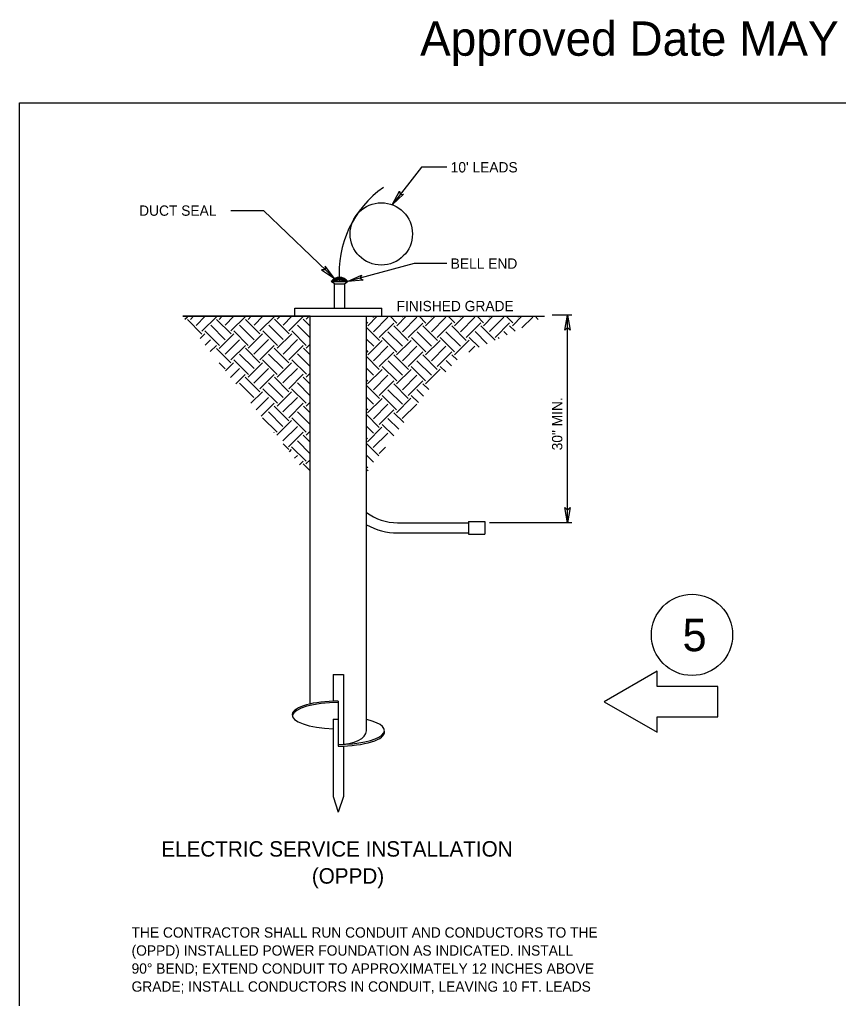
# Model space of a CAD drawing. Extents: x 99992 to 113392, y 99794 to 102182.
# Drawn here: x 105092 to 106046, y 101041 to 102182 of the extents above; entities that cross this region are included whole.
import ezdxf

# ---------------------------------------------------------------- set-up
doc = ezdxf.new("R2010")
doc.units = 0
for name, color, linetype in [('Border Line', 7, 'Continuous'), ('Border Organizer Shape', 7, 'Continuous'), ('Default', 7, 'Continuous'), ('QM Aggregate Gravel', 7, 'Continuous')]:
    doc.layers.add(name, color=color, linetype=linetype)

msp = doc.modelspace()

# ---------------------------------------------------------------- linework, layer by layer
at = {"layer": 'Border Organizer Shape'}
for p, q in [((105560.5, 102010), (105526.1, 101966.4)), ((105590, 102010), (105560.5, 102010)), ((105338.2, 101959.5), (105376.3, 101959.5)), ((105376.3, 101959.5), (105459, 101880.2)), ((105551.9, 101897.8), (105474.3, 101876.7)), ((105590, 101897.8), (105551.9, 101897.8)), ((105455.4, 101876.7), (105474.3, 101876.8)), ((105458.9, 101874), (105455.4, 101876.7)), ((105458.8, 101874), (105458.8, 101845.8)), ((105458.8, 101874), (105470.7, 101874)), ((105470.7, 101874), (105474.3, 101876.7)), ((105470.7, 101874), (105470.7, 101845.8)), ((105412.7, 101845.8), (105514.3, 101845.8)), ((105412.7, 101836.3), (105412.7, 101845.8)), ((105514.3, 101836.3), (105514.3, 101845.8)), ((105282.3, 101836.3), (105430.7, 101836.3)), ((105430.7, 101836.3), (105282.3, 101836.3)), ((105284.9, 101833), (105287.8, 101835.9)), ((105287.8, 101832.6), (105304.7, 101815.7)), ((105291.1, 101836.3), (105291.4, 101836)), ((105291.2, 101832.6), (105294.9, 101836.3)), ((105297.9, 101825.8), (105308.4, 101836.3)), ((105304.7, 101819), (105321.6, 101835.9)), ((105321.7, 101832.7), (105338.6, 101815.8)), ((105324.7, 101836.3), (105325, 101835.9)), ((105324.9, 101832.7), (105328.4, 101836.3)), ((105331.6, 101825.9), (105341.9, 101836.3)), ((105338.4, 101819.2), (105355.3, 101836.1)), ((105355.3, 101832.7), (105372.2, 101815.8)), ((105358.7, 101832.7), (105362.2, 101836.3)), ((105358.7, 101836.3), (105358.9, 101836.1)), ((105365.4, 101825.9), (105375.7, 101836.3)), ((105372.2, 101819.2), (105389.1, 101836.1)), ((105389.2, 101832.8), (105406.1, 101815.9)), ((105392.3, 101832.8), (105395.8, 101836.3)), ((105392.3, 101836.3), (105392.4, 101836.1)), ((105399.1, 101826), (105409.3, 101836.3)), ((105405.8, 101819.3), (105422.7, 101836.2)), ((105412.7, 101836.3), (105514.3, 101836.3)), ((105422.7, 101832.8), (105430.7, 101824.9)), ((105426.1, 101832.8), (105429.6, 101836.3)), ((105426.3, 101836.3), (105426.4, 101836.2)), ((105430.7, 101384.5), (105430.7, 101836.3)), ((105496.4, 101353.3), (105496.4, 101836.3)), ((105496.4, 101836.3), (105703.7, 101836.3)), ((105496.4, 101829.8), (105497.9, 101828.3)), ((105497.8, 101825.1), (105508.9, 101836.3)), ((105503.5, 101836.3), (105504.6, 101835.1)), ((105504.5, 101818.3), (105521.4, 101835.2)), ((105511.3, 101811.6), (105528.2, 101828.5)), ((105524, 101836.3), (105531.8, 101828.5)), ((105531.6, 101825.1), (105542.7, 101836.3)), ((105537.5, 101836.3), (105538.6, 101835.2)), ((105538.3, 101818.3), (105555.2, 101835.2)), ((105545.1, 101811.6), (105562, 101828.5)), ((105557.6, 101836.3), (105565.4, 101828.5)), ((105565.2, 101825.2), (105576.3, 101836.3)), ((105571.1, 101836.3), (105572.1, 101835.2)), ((105572, 101818.4), (105588.9, 101835.3)), ((105578.8, 101811.7), (105595.7, 101828.6)), ((105591.6, 101836.3), (105599.3, 101828.6)), ((105599, 101825.2), (105610.1, 101836.3)), ((105605.1, 101836.3), (105606, 101835.3)), ((105605.8, 101818.4), (105622.7, 101835.3)), ((105612.6, 101811.7), (105629.5, 101828.6)), ((105625.2, 101836.3), (105632.8, 101828.6)), ((105632.7, 101825.3), (105643.7, 101836.3)), ((105638.7, 101836.3), (105639.6, 101835.3)), ((105639.5, 101818.6), (105656.4, 101835.5)), ((105646.2, 101811.8), (105663.1, 101828.7)), ((105659.2, 101836.3), (105666.8, 101828.7)), ((105666.5, 101825.3), (105677.5, 101836.3)), ((105672.7, 101836.3), (105673.5, 101835.5)), ((105677.5, 101822.8), (105690.2, 101835.5)), ((105692.8, 101836.3), (105696.5, 101832.5)), ((105735.5, 101837.8), (105712.7, 101837.8)), ((105730.5, 101595.8), (105730.5, 101837.8)), ((105308.2, 101819.2), (105325.1, 101802.3)), ((105315, 101825.9), (105331.9, 101809)), ((105341.8, 101819.2), (105358.7, 101802.3)), ((105348.5, 101825.9), (105365.4, 101809)), ((105375.7, 101819.3), (105392.6, 101802.4)), ((105382.4, 101826), (105399.3, 101809.1)), ((105409.2, 101819.3), (105426.1, 101802.4)), ((105416, 101826), (105430.7, 101811.4)), ((105496.4, 101823.3), (105511.5, 101808.2)), ((105521.4, 101818.3), (105538.3, 101801.4)), ((105528.2, 101825.1), (105545.1, 101808.2)), ((105555.3, 101818.4), (105572.2, 101801.5)), ((105562.1, 101825.2), (105579, 101808.3)), ((105588.9, 101818.4), (105605.8, 101801.5)), ((105595.7, 101825.2), (105612.6, 101808.3)), ((105622.8, 101818.6), (105637, 101804.4)), ((105629.6, 101825.3), (105646.3, 101808.6)), ((105656.4, 101818.6), (105660.1, 101814.9)), ((105663.1, 101825.3), (105669.4, 101819.1)), ((105302.6, 101810.4), (105308, 101815.8)), ((105308.5, 101802.8), (105314.7, 101809)), ((105324.9, 101798.9), (105341.8, 101815.8)), ((105331.6, 101792.1), (105348.5, 101809)), ((105358.5, 101799), (105375.4, 101815.9)), ((105365.3, 101792.2), (105382.2, 101809.1)), ((105392.3, 101799), (105409.2, 101815.9)), ((105399.1, 101792.2), (105416, 101809.1)), ((105496.4, 101809.8), (105504.8, 101801.4)), ((105497.8, 101791.3), (105514.7, 101808.2)), ((105514.7, 101811.6), (105531.6, 101794.7)), ((105531.4, 101791.4), (105548.3, 101808.3)), ((105548.6, 101811.7), (105565.5, 101794.8)), ((105565.2, 101791.4), (105582.1, 101808.3)), ((105582.1, 101811.7), (105599, 101794.8)), ((105598.9, 101791.5), (105615.8, 101808.4)), ((105616.1, 101811.8), (105627.7, 101800.2)), ((105649.6, 101811.8), (105650.8, 101810.6)), ((105314.4, 101795.2), (105321.5, 101802.3)), ((105321.5, 101798.9), (105338.4, 101782)), ((105338.4, 101785.4), (105355.3, 101802.3)), ((105355.4, 101799), (105372.3, 101782.1)), ((105372.1, 101785.5), (105389, 101802.4)), ((105389, 101799), (105405.8, 101782.1)), ((105405.8, 101785.5), (105422.7, 101802.4)), ((105422.9, 101799.1), (105430.7, 101791.3)), ((105426, 101799.1), (105430.7, 101803.8)), ((105496.4, 101796.3), (105498, 101794.7)), ((105504.5, 101784.5), (105521.4, 101801.4)), ((105511.3, 101777.8), (105528.2, 101794.7)), ((105538.2, 101784.6), (105555.1, 101801.5)), ((105545, 101777.9), (105561.9, 101794.8)), ((105572, 101784.6), (105588.9, 101801.5)), ((105578.8, 101777.9), (105595.7, 101794.8)), ((105615.6, 101794.7), (105622.6, 101801.7)), ((105341.9, 101785.5), (105358.8, 101768.6)), ((105348.6, 101792.2), (105365.5, 101775.3)), ((105375.4, 101785.5), (105392.3, 101768.6)), ((105382.2, 101792.2), (105399.1, 101775.3)), ((105409.4, 101785.6), (105426.3, 101768.7)), ((105416.1, 101792.4), (105430.7, 101777.8)), ((105496.4, 101789.3), (105511.3, 101774.4)), ((105521.6, 101784.6), (105538.5, 101767.7)), ((105528.3, 101791.4), (105545.2, 101774.5)), ((105555.1, 101784.6), (105572, 101767.7)), ((105561.9, 101791.4), (105578.8, 101774.5)), ((105589, 101784.8), (105595.2, 101778.6)), ((105595.8, 101791.5), (105601.8, 101785.5)), ((105324.7, 101782.2), (105331.6, 101775.2)), ((105332.1, 101772.6), (105341.6, 101782.1)), ((105338.1, 101765), (105348.4, 101775.3)), ((105358.5, 101765.2), (105375.4, 101782.1)), ((105365.3, 101758.4), (105382.2, 101775.3)), ((105392.2, 101765.3), (105409.1, 101782.2)), ((105399, 101758.6), (105415.9, 101775.5)), ((105496.4, 101775.8), (105504.5, 101767.6)), ((105497.7, 101757.6), (105514.5, 101774.5)), ((105514.8, 101777.9), (105531.7, 101761)), ((105531.4, 101757.6), (105548.3, 101774.5)), ((105548.3, 101777.9), (105565.2, 101761)), ((105565.1, 101757.7), (105582, 101774.6)), ((105582.3, 101778), (105588.6, 101771.6)), ((105344, 101757.5), (105355.2, 101768.6)), ((105355.2, 101765.2), (105372.1, 101748.3)), ((105372.1, 101751.7), (105389, 101768.6)), ((105389.1, 101765.3), (105406, 101748.4)), ((105405.7, 101751.8), (105422.6, 101768.7)), ((105422.6, 101765.3), (105430.7, 101757.3)), ((105426, 101765.3), (105430.7, 101770)), ((105496.4, 101762.2), (105497.8, 101760.9)), ((105504.4, 101750.8), (105521.3, 101767.7)), ((105511.2, 101744.1), (105528.1, 101761)), ((105538.2, 101750.8), (105555.1, 101767.7)), ((105545, 101744.1), (105561.9, 101761)), ((105348.4, 101758.4), (105365.3, 101741.5)), ((105361.8, 101734.9), (105375.3, 101748.4)), ((105375.6, 101751.8), (105392.5, 101734.9)), ((105382.3, 101758.6), (105399.2, 101741.7)), ((105392.2, 101731.5), (105409.1, 101748.4)), ((105409.1, 101751.8), (105426, 101734.9)), ((105415.9, 101758.6), (105430.7, 101743.8)), ((105496.4, 101755.7), (105511.4, 101740.7)), ((105521.3, 101750.8), (105538.2, 101733.9)), ((105528.1, 101757.6), (105545, 101740.7)), ((105555.2, 101751), (105562.8, 101743.4)), ((105562, 101757.7), (105568.8, 101750.9)), ((105367.8, 101727.3), (105382.1, 101741.7)), ((105399, 101724.8), (105415.9, 101741.7)), ((105496.4, 101742.2), (105504.7, 101734)), ((105497.7, 101723.8), (105514.5, 101740.7)), ((105514.5, 101744.1), (105531.4, 101727.2)), ((105531.3, 101723.9), (105548.2, 101740.8)), ((105548.5, 101744.2), (105557, 101735.7)), ((105373.7, 101719.8), (105388.8, 101734.9)), ((105388.8, 101731.5), (105405.7, 101714.6)), ((105405.7, 101718), (105422.6, 101734.9)), ((105422.8, 101731.6), (105430.7, 101723.7)), ((105425.9, 101731.6), (105430.7, 101736.4)), ((105496.4, 101728.7), (105497.9, 101727.2)), ((105504.4, 101717), (105521.3, 101733.9)), ((105511.2, 101710.3), (105528.1, 101727.2)), ((105538.1, 101717.2), (105555, 101734.1)), ((105375.3, 101718), (105392.2, 101701.1)), ((105382.1, 101724.8), (105399, 101707.9)), ((105392.1, 101697.8), (105409, 101714.7)), ((105409.2, 101718.1), (105426.1, 101701.2)), ((105416, 101724.9), (105430.7, 101710.2)), ((105496.4, 101721.7), (105511.2, 101706.9)), ((105521.4, 101717.2), (105533.9, 101704.7)), ((105528.2, 101723.9), (105539.7, 101712.4)), ((105398.9, 101691.1), (105415.8, 101708)), ((105425.9, 101697.8), (105430.7, 101702.6)), ((105496.4, 101708.2), (105504.4, 101700.1)), ((105497.5, 101690.1), (105514.4, 101707)), ((105514.7, 101710.4), (105528.1, 101697)), ((105388.7, 101700.9), (105388.8, 101701.1)), ((105405.6, 101684.3), (105422.5, 101701.2)), ((105422.5, 101697.8), (105430.7, 101689.7)), ((105496.4, 101694.6), (105497.7, 101693.4)), ((105504.3, 101683.4), (105521.2, 101700.3)), ((105399.2, 101687.6), (105405.9, 101681)), ((105406.5, 101678.4), (105409, 101680.9)), ((105409, 101684.3), (105425.9, 101667.4)), ((105415.8, 101691.1), (105430.7, 101676.2)), ((105496.4, 101688.1), (105510.8, 101673.7)), ((105511.1, 101676.6), (105518.5, 101684)), ((105412.4, 101670.9), (105415.8, 101674.2)), ((105425.8, 101664.2), (105430.7, 101669.1)), ((105496.4, 101674.6), (105504.5, 101666.5)), ((105418.4, 101663.3), (105422.5, 101667.4)), ((105422.6, 101664.2), (105430.7, 101656.1)), ((105496.4, 101661.1), (105497.8, 101659.7)), ((105497.5, 101656.3), (105498.5, 101657.3)), ((105532.6, 101595.8), (105615.1, 101595.8)), ((105615.1, 101597.3), (105615.1, 101582.3)), ((105615.1, 101597.3), (105634.3, 101597.3)), ((105634.3, 101597.3), (105634.3, 101582.3)), ((105735.5, 101595.8), (105639.5, 101595.8)), ((105532.6, 101583.8), (105615.1, 101583.8)), ((105615.1, 101582.3), (105634.3, 101582.3)), ((105457.6, 101418.7), (105469.5, 101418.7)), ((105457.6, 101418.7), (105457.6, 101387.8)), ((105469.5, 101418.7), (105469.5, 101337.9)), ((105463.5, 101387.9), (105463.5, 101335.4)), ((105457.6, 101366.8), (105457.6, 101276.5)), ((105457.6, 101366.8), (105463.5, 101366.8)), ((105469.5, 101335.3), (105469.5, 101276.5)), ((105457.6, 101276.5), (105463.5, 101258.6)), ((105469.5, 101276.5), (105463.5, 101258.6))]:
    msp.add_line(p, q, dxfattribs=at)
for points in [[(105539.5, 101978.5), (105526.1, 101966.4), (105534.7, 101982.3), (105535.4, 101978.2)], [(105444, 101890.4), (105459, 101880.2), (105448.2, 101894.7), (105448.1, 101890.6)], [(105492.3, 101878.5), (105474.3, 101876.7), (105490.7, 101884.3), (105488.8, 101880.7)], [(105727.5, 101820), (105730.5, 101837.8), (105733.5, 101820), (105730.5, 101822.8)], [(105733.5, 101613.6), (105730.5, 101595.8), (105727.5, 101613.6), (105730.5, 101610.8)]]:
    msp.add_lwpolyline(points, close=True, dxfattribs=at)
msp.add_lwpolyline([(105282.3, 101836.3), (105430.7, 101836.3)], dxfattribs=at)
msp.add_circle((105513.6, 101932.3), 36.3, dxfattribs=at)
for centre, radius, start, end in [((105586.5, 101886.8), 122.1, 125.1734, 184.5157), ((105464.9, 101870.6), 11.3, 33.0809, 146.9191), ((105464.9, 101867.2), 13.5, 45.2165, 134.7835), ((105464.9, 101861.9), 17.6, 57.4388, 122.5612), ((105464.9, 101848.2), 30.1, 71.589, 108.411), ((105532.6, 101657.6), 61.8, 234.1622, 270.0222), ((105532.6, 101657.6), 73.7, 240.6148, 270.0222)]:
    msp.add_arc(centre, radius, start, end, dxfattribs=at)
for centre, major_axis, ratio, start_param, end_param in [((105463.8, 101371.7), (54.2, 0), 0.298969, 1.579309, 4.602023), ((105463.8, 101369.9), (54.2, 0), 0.298969, 1.576397, 3.062958), ((105463, 101353.6), (-54.2, 0), 0.298969, 1.576478, 4.042496), ((105463.5, 101353.2), (32.9, 0), 0.482136, 4.712389, 6.283185), ((105463.2, 101351.6), (-54.2, 0), 0.298969, 1.576478, 3.180482)]:
    msp.add_ellipse(centre, major_axis=major_axis, ratio=ratio, start_param=start_param, end_param=end_param, dxfattribs=at)
at = {"layer": 'Default'}
msp.add_lwpolyline([(105092.2, 102085.3), (108291.9, 102085.3), (108291.9, 99885.7), (105092.2, 99885.7)], close=True, dxfattribs=at)
at = {"layer": 'QM Aggregate Gravel'}
msp.add_lwpolyline([(105773.4, 101387.1), (105834.8, 101351.6), (105834.8, 101369.4), (105905.8, 101369.4), (105905.8, 101404.8), (105834.8, 101404.8), (105834.8, 101422.6)], close=True, dxfattribs=at)
msp.add_circle((105875.6, 101465), 47.3, dxfattribs=at)

# ---------------------------------------------------------------- texts
at = {"layer": 'Border Line'}
msp.add_text('Approved Date MAY 2020', height=40, dxfattribs=at).set_placement((105558.8, 102140))
at = {"layer": 'Border Organizer Shape'}
for s, height, p in [(" 10' LEADS", 12, (105590, 102004)), ('DUCT SEAL ', 12, (105231.5, 101953.5)), (' BELL END', 12, (105590, 101891.8)), ('FINISHED GRADE', 12, (105531.4, 101842.3)), ('ELECTRIC SERVICE INSTALLATION ', 18, (105257.3, 101206.6)), ('(OPPD)', 18, (105432.7, 101175.1)), ('THE CONTRACTOR SHALL RUN CONDUIT AND CONDUCTORS TO THE ', 12, (105222.7, 101112.2)), ('(OPPD) INSTALLED POWER FOUNDATION AS INDICATED. INSTALL ', 12, (105222.7, 101091.2)), ('90° BEND; EXTEND CONDUIT TO APPROXIMATELY 12 INCHES ABOVE ', 12, (105222.7, 101070.2)), ('GRADE; INSTALL CONDUCTORS IN CONDUIT, LEAVING 10 FT. LEADS ', 12, (105222.7, 101049.2))]:
    msp.add_text(s, height=height, dxfattribs=at).set_placement(p)
msp.add_text('30" MIN.', height=12, rotation=90, dxfattribs=at).set_placement((105724.5, 101680.1))
at = {"layer": 'QM Aggregate Gravel'}
msp.add_text('5', height=37.8, dxfattribs=at).set_placement((105864.5, 101446))

doc.saveas('drawing.dxf')
